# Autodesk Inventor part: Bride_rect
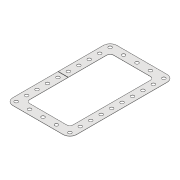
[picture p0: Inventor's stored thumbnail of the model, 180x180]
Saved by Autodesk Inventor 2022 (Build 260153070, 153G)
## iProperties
Created: 2021-07
Part Number: Bride_rect
Material: Générique
Document SubType Name: Sheet Metal
Designer: Fabian
Density: 1 g/cm^3
Flat Pattern Width: 19 cm
Flat Pattern Length: 31 cm
Flat Pattern Area: 589 cm^2
Sheet Metal Rule: Par défaut_mm
Sheet Metal Width: 190,000 mm
Sheet Metal Length: 310,000 mm
Sheet Metal Area: 58900,000 mm^2
Appearance: Par défaut
Author: Fabian
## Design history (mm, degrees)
derived "Tremie.ipt"
sketch "Esquisse1"
  geometry: L1 (155, 15)-(-5, 15); L2 (-5, 15)-(-5, 295); L3 (-5, 295)-(155, 295); L4 (155, 295)-(155, 15); L5 (155, 15)-(-5, 295); L6 (-5, 15)-(155, 295); L7 (0, 310)-(150, 310) reference; L8 (170, 290)-(170, 20) reference; L9 (-20, 155.5)-(-20, 290) reference; L10 (150, 0)-(0, 0) reference; 1 further point
  constraints: 12 end point, 2 midpoint, 2 parallel, 1 horizontal, 1 perpendicular
  dimensions: "d4" = 15 distance between parallel lines of L3 L7; "d5" = 15 distance between parallel lines of L8 L4 (= d4); "d6" = 15 distance between parallel lines of L9 L2 (= d4); "d7" = 15 distance between parallel lines of L10 L1 (= d4); "d15" = 280 distance of L3.end L1.start (derived); "d16" = 160 distance of L2.end L3.end (derived)
hole "Perçage1" sketch "Esquisse1" at (155, 15) diameter "d8" = 10; stored, may be unused: countersink angle "d12" = 90 deg, drill point angle "d14" = 118 deg; dims "d9" = 6, "d10" = 4, "d11" = 2, "d13" = 0.5 (= Epaisseur)
pattern_linear "Réseau rectangulaire2" dims "d25" = 160 (= d16), "d31" = 280 (= d15)
feature "Bride_rect::Tremie.ipt" dims "d0" = 10
tag "FonctionRepérage1"
node "Solide1"
feature "Définition1"
other parameters: "Epaisseur" = 0.5 (derived), "RayonPli" = 0.5 (= Epaisseur), "LargeurGrugeage" = 0.5 (= Epaisseur), "ProfondeurGrugeage" = 0.25 (= 0.5 x Epaisseur), "TailleGrugeage" = 2 (= 4 x Epaisseur), "SeamGap" = 0.01, "RestesMinimum" = 1 (= 2 x Epaisseur), "Rayondetransition" = 0.5 (= RayonPli), "TailleRayonJacobi" = 0.5 (= RayonPli), "TailleJeu" = 0.5 (= Epaisseur), "d1" = 0.5 (= Epaisseur), "Epaisseur" = 0.5, "LargeurGrugeage" = 0.5, "ProfondeurGrugeage" = 0.25, "RayonPli" = 0.5, "Rayondetransition" = 0.5, "RestesMinimum" = 1, "TailleGrugeage" = 2, "TailleJeu" = 0.5, "TailleRayonJacobi" = 0.5
